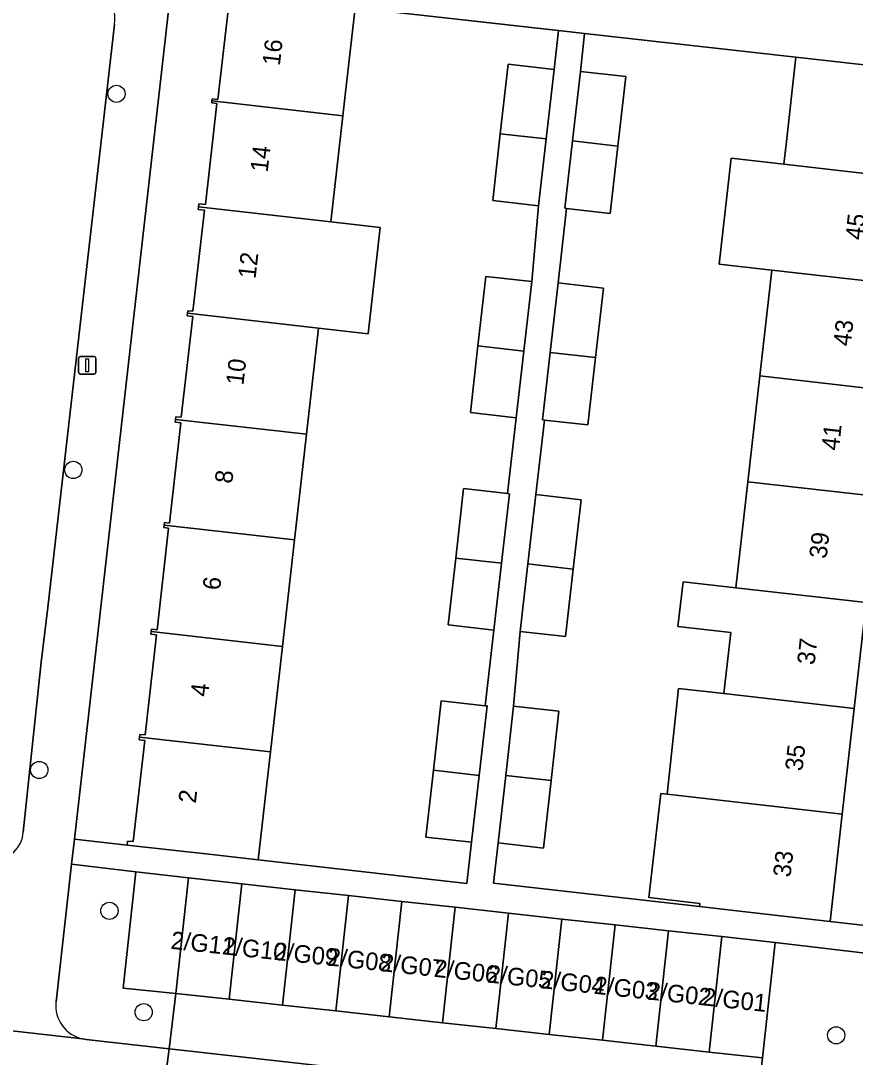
# Model space of a CAD drawing. Extents: x 161928 to 163071, y 386474 to 387428.
# Drawn here: x 162142.2 to 162189.6, y 386750 to 386808.8 of the extents above; entities that cross this region are included whole.
import ezdxf

# ---------------------------------------------------------------- set-up
doc = ezdxf.new("R2010")
doc.units = 0
for name, color, linetype in [('IMGEO_Boom', 7, 'Continuous'), ('IMGEO_Erf', 7, 'Continuous'), ('IMGEO_Groenvoorziening', 7, 'Continuous'), ('IMGEO_Lichtmast', 7, 'Continuous'), ('IMGEO_Muur', 7, 'Continuous'), ('IMGEO_Pand', 7, 'Continuous'), ('IMGEO_Pand_nummerreeks', 7, 'Continuous'), ('IMGEO_Parkeervlak_open', 7, 'Continuous'), ('IMGEO_Voetpad_open', 7, 'Continuous')]:
    doc.layers.add(name, color=color, linetype=linetype)

msp = doc.modelspace()

# ---------------------------------------------------------------- linework, layer by layer
at = {"layer": 'IMGEO_Boom'}
for centre in [(162147.632, 386804.669), (162145.179, 386783.309), (162143.245, 386766.27), (162147.229, 386758.27), (162149.178, 386752.512), (162188.511, 386751.201)]:
    msp.add_circle(centre, 0.489, dxfattribs=at)
at = {"layer": 'IMGEO_Erf'}
msp.add_lwpolyline([(162150.735, 386810.737), (162145.246, 386762.348), (162148.24, 386762.008), (162148.266, 386762.236), (162148.588, 386762.2), (162149.241, 386767.949), (162148.918, 386767.985), (162148.935, 386768.138), (162148.952, 386768.291), (162149.253, 386768.257), (162149.9, 386773.952), (162149.588, 386773.987), (162149.604, 386774.128), (162149.62, 386774.271), (162149.936, 386774.235), (162150.592, 386780.009), (162150.319, 386780.04), (162150.335, 386780.18), (162150.351, 386780.318), (162150.645, 386780.285), (162151.292, 386785.98), (162150.964, 386786.018), (162150.982, 386786.178), (162151, 386786.333), (162151.314, 386786.298), (162151.964, 386792.023), (162151.655, 386792.058), (162151.672, 386792.205), (162151.688, 386792.35), (162151.974, 386792.317), (162152.625, 386798.052), (162152.275, 386798.092), (162152.294, 386798.255), (162152.313, 386798.422), (162152.679, 386798.38), (162153.331, 386804.114), (162153.039, 386804.147), (162153.052, 386804.265), (162153.066, 386804.387), (162153.392, 386804.35), (162154.044, 386810.089)], dxfattribs=at)
for points in [[(162170.339, 386786.265), (162167.735, 386786.562), (162168.166, 386790.351), (162168.616, 386794.301), (162171.221, 386794.004), (162171.607, 386798.314), (162169.003, 386798.611), (162169.434, 386802.4), (162169.884, 386806.35), (162172.489, 386806.053), (162172.739, 386808.261), (162161.181, 386809.554), (162160.617, 386804.586), (162160.485, 386803.42), (162159.801, 386797.402), (162162.607, 386797.083), (162161.919, 386791.04), (162159.114, 386791.359), (162158.429, 386785.331), (162157.748, 386779.337), (162157.06, 386773.28), (162156.38, 386767.292), (162155.683, 386761.162), (162167.535, 386759.816), (162167.803, 386762.166), (162165.199, 386762.463), (162165.63, 386766.252), (162166.08, 386770.202), (162168.581, 386769.917), (162169.071, 386774.216), (162166.467, 386774.513), (162166.898, 386778.302), (162167.348, 386782.252), (162169.849, 386781.967)], [(162184.172, 386788.644), (162184.854, 386794.655), (162181.868, 386794.994), (162182.55, 386801.006), (162185.536, 386800.667), (162185.663, 386801.789), (162186.227, 386806.757), (162174.222, 386808.093), (162173.982, 386805.938), (162176.557, 386805.645), (162176.108, 386801.705), (162175.672, 386797.875), (162173.199, 386798.156), (162172.718, 386793.925), (162175.293, 386793.632), (162174.844, 386789.691), (162174.408, 386785.862), (162171.935, 386786.143), (162171.454, 386781.912), (162174.029, 386781.619), (162173.58, 386777.679), (162173.144, 386773.849), (162170.569, 386774.142), (162170.19, 386769.899), (162172.765, 386769.606), (162172.316, 386765.666), (162171.88, 386761.836), (162169.305, 386762.129), (162169.044, 386759.836), (162180.754, 386758.509), (162180.774, 386758.688), (162177.874, 386759.018), (162178.544, 386764.928), (162178.902, 386764.887), (162179.555, 386770.89), (162182.127, 386770.61), (162182.52, 386774.076), (162179.525, 386774.416), (162179.813, 386776.961), (162182.808, 386776.621), (162183.49, 386782.633)], [(162196.771, 386805.559), (162193.639, 386805.915), (162192.948, 386799.826), (162192.266, 386793.814), (162191.584, 386787.803), (162190.903, 386781.792), (162190.221, 386775.78), (162189.539, 386769.769), (162188.857, 386763.757), (162188.166, 386757.668), (162191.31, 386757.312)]]:
    msp.add_lwpolyline(points, close=True, dxfattribs=at)
at = {"layer": 'IMGEO_Groenvoorziening'}
for points in [[(162148.735, 386760.491), (162145.084, 386760.923), (162144.196, 386753.098)], [(162145.709, 386750.996), (162145.903, 386750.964), (162150.631, 386750.435), (162150.994, 386753.584), (162148.009, 386753.883), (162148.735, 386760.491)], [(162190.23, 386747.764), (162191.133, 386755.746), (162185.046, 386756.474), (162184.326, 386749.92), (162183.946, 386746.708), (162183.925, 386746.534), (162187.908, 386746.108)]]:
    msp.add_lwpolyline(points, dxfattribs=at)
msp.add_lwpolyline([(162150.994, 386753.584), (162151.714, 386760.138), (162148.735, 386760.491), (162148.009, 386753.883)], close=True, dxfattribs=at)
msp.add_arc((162146.118, 386752.886), 1.934, 173.71496, 257.77702, dxfattribs=at)
at = {"layer": 'IMGEO_Lichtmast'}
for p, q in [((162145.475, 386788.848), (162145.475, 386789.648)), ((162145.475, 386789.648), (162145.475, 386788.848)), ((162145.575, 386789.748), (162146.365, 386789.748)), ((162146.365, 386789.748), (162145.575, 386789.748)), ((162146.465, 386789.648), (162146.465, 386788.848)), ((162146.465, 386788.848), (162146.465, 386789.648)), ((162146.365, 386788.748), (162145.575, 386788.748)), ((162145.575, 386788.748), (162146.365, 386788.748))]:
    msp.add_line(p, q, dxfattribs=at)
msp.add_lwpolyline([(162145.895, 386789.623), (162146.045, 386789.623), (162146.045, 386788.873), (162145.895, 386788.873), (162145.895, 386789.623)], dxfattribs=at)
for centre, start, end in [((162145.575, 386789.648), 90, 180), ((162145.575, 386789.648), 90, 180), ((162146.365, 386789.648), 0, 90), ((162146.365, 386789.648), 360, 90), ((162145.575, 386788.848), 180, 270), ((162145.575, 386788.848), 180, 270), ((162146.365, 386788.848), 270, 0), ((162146.365, 386788.848), 270, 0)]:
    msp.add_arc(centre, 0.1, start, end, dxfattribs=at)
at = {"layer": 'IMGEO_Muur'}
for points in [[(162161.181, 386809.554), (162172.883, 386808.245)], [(162174.385, 386808.075), (162186.227, 386806.757)]]:
    msp.add_lwpolyline(points, dxfattribs=at)
at = {"layer": 'IMGEO_Pand'}
for points in [[(162153.738, 386810.4), (162153.707, 386810.127), (162154.044, 386810.089), (162153.392, 386804.35), (162153.066, 386804.387), (162153.052, 386804.265), (162160.485, 386803.42), (162160.617, 386804.586), (162161.181, 386809.554)], [(162186.227, 386806.757), (162185.663, 386801.789), (162185.536, 386800.667), (162192.948, 386799.826), (162193.639, 386805.915)], [(162172.039, 386802.105), (162172.489, 386806.053), (162169.884, 386806.35), (162169.434, 386802.4)], [(162176.108, 386801.705), (162176.557, 386805.645), (162173.982, 386805.938), (162173.533, 386801.997)], [(162159.801, 386797.402), (162160.485, 386803.42), (162153.052, 386804.265), (162153.039, 386804.147), (162153.331, 386804.114), (162152.679, 386798.38), (162152.313, 386798.422), (162152.294, 386798.255)], [(162169.434, 386802.4), (162169.003, 386798.611), (162171.607, 386798.314), (162172.039, 386802.105)], [(162176.108, 386801.705), (162173.533, 386801.997), (162173.097, 386798.168), (162173.199, 386798.156), (162175.672, 386797.875)], [(162192.948, 386799.826), (162185.536, 386800.667), (162182.55, 386801.006), (162181.868, 386794.994), (162184.854, 386794.655), (162192.266, 386793.814)], [(162159.801, 386797.402), (162152.294, 386798.255), (162152.275, 386798.092), (162152.625, 386798.052), (162151.974, 386792.317), (162151.688, 386792.35), (162151.672, 386792.205), (162159.114, 386791.359), (162161.919, 386791.04), (162162.607, 386797.083)], [(162171.221, 386794.004), (162168.616, 386794.301), (162168.166, 386790.351), (162170.771, 386790.056)], [(162191.584, 386787.803), (162192.266, 386793.814), (162184.854, 386794.655), (162184.172, 386788.644)], [(162175.293, 386793.632), (162172.718, 386793.925), (162172.269, 386789.984), (162174.844, 386789.691)], [(162158.429, 386785.331), (162159.114, 386791.359), (162151.672, 386792.205), (162151.655, 386792.058), (162151.964, 386792.023), (162151.314, 386786.298), (162151, 386786.333), (162150.982, 386786.178)], [(162167.735, 386786.562), (162170.339, 386786.265), (162170.771, 386790.056), (162168.166, 386790.351)], [(162174.844, 386789.691), (162172.269, 386789.984), (162171.833, 386786.155), (162171.935, 386786.143), (162174.408, 386785.862)], [(162184.172, 386788.644), (162183.49, 386782.633), (162190.903, 386781.792), (162191.584, 386787.803)], [(162157.748, 386779.337), (162158.429, 386785.331), (162150.982, 386786.178), (162150.964, 386786.018), (162151.292, 386785.98), (162150.645, 386780.285), (162150.351, 386780.318), (162150.335, 386780.18)], [(162190.221, 386775.78), (162190.903, 386781.792), (162183.49, 386782.633), (162182.808, 386776.621)], [(162169.953, 386781.955), (162169.849, 386781.967), (162167.348, 386782.252), (162166.898, 386778.302), (162169.503, 386778.007)], [(162174.029, 386781.619), (162171.454, 386781.912), (162171.005, 386777.971), (162173.58, 386777.679)], [(162150.335, 386780.18), (162150.319, 386780.04), (162150.592, 386780.009), (162149.936, 386774.235), (162149.62, 386774.271), (162149.604, 386774.128), (162157.06, 386773.28), (162157.748, 386779.337)], [(162166.467, 386774.513), (162169.071, 386774.216), (162169.503, 386778.007), (162166.898, 386778.302)], [(162170.569, 386774.142), (162173.144, 386773.849), (162173.58, 386777.679), (162171.005, 386777.971)], [(162190.221, 386775.78), (162182.808, 386776.621), (162179.813, 386776.961), (162179.525, 386774.416), (162182.52, 386774.076), (162182.127, 386770.61), (162189.539, 386769.769)], [(162156.38, 386767.292), (162157.06, 386773.28), (162149.604, 386774.128), (162149.588, 386773.987), (162149.9, 386773.952), (162149.253, 386768.257), (162148.952, 386768.291), (162148.935, 386768.138)], [(162189.539, 386769.769), (162182.127, 386770.61), (162179.555, 386770.89), (162178.902, 386764.887), (162188.857, 386763.757)], [(162168.685, 386769.905), (162168.581, 386769.917), (162166.08, 386770.202), (162165.63, 386766.252), (162168.235, 386765.957)], [(162172.765, 386769.606), (162170.19, 386769.899), (162169.741, 386765.958), (162172.316, 386765.666)], [(162148.935, 386768.138), (162148.918, 386767.985), (162149.241, 386767.949), (162148.588, 386762.2), (162148.266, 386762.236), (162148.24, 386762.008), (162153.209, 386761.443), (162155.683, 386761.162), (162156.38, 386767.292)], [(162165.199, 386762.463), (162167.803, 386762.166), (162168.235, 386765.957), (162165.63, 386766.252)], [(162169.305, 386762.129), (162171.88, 386761.836), (162172.316, 386765.666), (162169.741, 386765.958)], [(162188.857, 386763.757), (162178.902, 386764.887), (162178.544, 386764.928), (162177.874, 386759.018), (162180.774, 386758.688), (162180.754, 386758.509), (162183.198, 386758.232), (162188.166, 386757.668)], [(162154.024, 386753.251), (162154.744, 386759.805), (162151.714, 386760.138), (162150.994, 386753.584)], [(162157.054, 386752.918), (162157.774, 386759.472), (162154.744, 386759.805), (162154.024, 386753.251)], [(162160.084, 386752.585), (162160.805, 386759.139), (162157.774, 386759.472), (162157.054, 386752.918)], [(162163.114, 386752.252), (162163.835, 386758.806), (162160.805, 386759.139), (162160.084, 386752.585)], [(162166.144, 386751.919), (162166.865, 386758.473), (162163.835, 386758.806), (162163.114, 386752.252)], [(162169.175, 386751.585), (162169.895, 386758.139), (162166.865, 386758.473), (162166.144, 386751.919)], [(162172.205, 386751.252), (162172.925, 386757.806), (162169.895, 386758.139), (162169.175, 386751.585)], [(162175.235, 386750.919), (162175.955, 386757.473), (162172.925, 386757.806), (162172.205, 386751.252)], [(162178.265, 386750.586), (162178.986, 386757.14), (162175.955, 386757.473), (162175.235, 386750.919)], [(162181.295, 386750.253), (162182.016, 386756.807), (162178.986, 386757.14), (162178.265, 386750.586)], [(162183.598, 386750), (162184.326, 386749.92), (162185.046, 386756.474), (162182.016, 386756.807), (162181.295, 386750.253)]]:
    msp.add_lwpolyline(points, close=True, dxfattribs=at)
at = {"layer": 'IMGEO_Parkeervlak_open'}
for points in [[(162146.433, 386799.153), (162147.51, 386808.606)], [(162142.34, 386762.729), (162143.355, 386772.386), (162143.739, 386775.502), (162146.433, 386799.153)]]:
    msp.add_lwpolyline(points, dxfattribs=at)
for centre, radius, start, end in [((162145.336, 386808.956), 2.202, 350.85616, 84.46814), ((162140.605, 386762.861), 1.74, 271.83363, 355.65594)]:
    msp.add_arc(centre, radius, start, end, dxfattribs=at)
at = {"layer": 'IMGEO_Voetpad_open'}
for points in [[(162188.169, 386809.596), (162188.037, 386809.606), (162184.856, 386809.988), (162178.91, 386810.626), (162177.866, 386810.736), (162174.11, 386811.153), (162170.302, 386811.315), (162155.965, 386812.861), (162151.055, 386813.427), (162150.735, 386810.737), (162153.738, 386810.4), (162161.181, 386809.554), (162172.739, 386808.261), (162174.222, 386808.093), (162186.227, 386806.757), (162193.639, 386805.915), (162196.771, 386805.559), (162197.044, 386808.424), (162195.251, 386808.624)], [(162184.326, 386749.92), (162183.598, 386750), (162181.295, 386750.253), (162178.265, 386750.586), (162175.235, 386750.919), (162172.205, 386751.252), (162169.175, 386751.585), (162166.144, 386751.919), (162163.114, 386752.252), (162160.084, 386752.585), (162157.054, 386752.918), (162154.024, 386753.251), (162150.994, 386753.584), (162150.631, 386750.435), (162154.519, 386750), (162183.946, 386746.708)]]:
    msp.add_lwpolyline(points, close=True, dxfattribs=at)
for points in [[(162144.196, 386753.098), (162145.084, 386760.923), (162145.246, 386762.348), (162150.735, 386810.737)], [(162147.51, 386808.606), (162146.433, 386799.153), (162143.739, 386775.502), (162143.355, 386772.386), (162142.34, 386762.729)], [(162191.31, 386757.312), (162188.166, 386757.668), (162183.198, 386758.232), (162180.754, 386758.509), (162169.044, 386759.836), (162169.305, 386762.129), (162169.741, 386765.958), (162170.19, 386769.899), (162170.569, 386774.142), (162171.005, 386777.971), (162171.454, 386781.912), (162171.935, 386786.143), (162171.833, 386786.155), (162172.269, 386789.984), (162172.718, 386793.925), (162173.199, 386798.156), (162173.097, 386798.168), (162173.533, 386801.997), (162173.982, 386805.938), (162174.222, 386808.093), (162172.739, 386808.261), (162172.489, 386806.053), (162172.039, 386802.105), (162171.607, 386798.314), (162171.221, 386794.004), (162170.771, 386790.056), (162170.339, 386786.265), (162169.849, 386781.967), (162169.953, 386781.955), (162169.503, 386778.007), (162169.071, 386774.216), (162168.581, 386769.917), (162168.685, 386769.905), (162168.235, 386765.957), (162167.803, 386762.166), (162167.535, 386759.816), (162155.683, 386761.162), (162153.209, 386761.443), (162148.24, 386762.008), (162145.246, 386762.348), (162145.084, 386760.923), (162148.735, 386760.491), (162151.714, 386760.138), (162154.744, 386759.805), (162157.774, 386759.472), (162160.805, 386759.139), (162163.835, 386758.806), (162166.865, 386758.473), (162169.895, 386758.139), (162172.925, 386757.806), (162175.955, 386757.473), (162178.986, 386757.14), (162182.016, 386756.807), (162185.046, 386756.474), (162191.133, 386755.746)], [(162135.66, 386759.762), (162134.807, 386752.229), (162145.709, 386750.996)], [(162145.903, 386750.964), (162145.709, 386750.996), (162134.807, 386752.229), (162129.914, 386752.746), (162127.26, 386753.058), (162122.784, 386753.584), (162122.596, 386751.923)], [(162150.388, 386748.693), (162150.57, 386750), (162150.631, 386750.435), (162145.903, 386750.964)], [(162183.817, 386745.423), (162183.925, 386746.534), (162183.946, 386746.708), (162154.519, 386750), (162150.631, 386750.435), (162150.57, 386750), (162150.388, 386748.693)]]:
    msp.add_lwpolyline(points, dxfattribs=at)
for centre, radius, start, end in [((162145.336, 386808.956), 2.202, 350.85616, 84.46814), ((162140.605, 386762.861), 1.74, 271.83363, 355.65594), ((162146.118, 386752.886), 1.934, 173.71496, 257.77702)]:
    msp.add_arc(centre, radius, start, end, dxfattribs=at)

# ---------------------------------------------------------------- texts
at = {"layer": 'IMGEO_Pand_nummerreeks'}
for s, rotation, p in [('16', 83.50031, (162156.907, 386806.235)), ('14', 83.50031, (162156.218, 386800.186)), ('45', 83.52579, (162190.016, 386796.332)), ('12', 83.50287, (162155.527, 386794.134)), ('43', 83.5282, (162189.332, 386790.301)), ('10', 83.50031, (162154.839, 386788.092)), ('41', 83.5282, (162188.66, 386784.382)), ('8', 83.50031, (162154.202, 386782.501)), ('39', 83.5282, (162187.964, 386778.239)), ('6', 83.50031, (162153.513, 386776.448)), ('37', 83.52579, (162187.28, 386772.208)), ('4', 83.50031, (162152.824, 386770.399)), ('35', 83.52579, (162186.596, 386766.177)), ('2', 83.50031, (162152.134, 386764.349)), ('33', 83.52579, (162185.912, 386760.146)), ('2/G11', 353.93508, (162150.68, 386756.119)), ('2/G10', 353.93508, (162153.604, 386755.808)), ('2/G09', 353.93508, (162156.537, 386755.496)), ('2/G08', 353.93508, (162159.574, 386755.174)), ('2/G07', 353.93508, (162162.601, 386754.852)), ('2/G06', 353.93508, (162165.631, 386754.53)), ('2/G05', 353.93508, (162168.661, 386754.208)), ('2/G04', 353.93508, (162171.692, 386753.886)), ('2/G03', 353.93508, (162174.722, 386753.564)), ('2/G02', 353.93508, (162177.746, 386753.243)), ('2/G01', 353.93508, (162180.892, 386752.909))]:
    msp.add_text(s, height=1, rotation=rotation, dxfattribs=at).set_placement(p)

doc.saveas('drawing.dxf')
